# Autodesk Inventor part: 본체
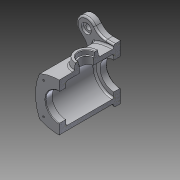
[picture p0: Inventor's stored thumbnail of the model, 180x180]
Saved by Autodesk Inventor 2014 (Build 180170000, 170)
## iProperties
Created: 2016-05
Part Number: 본체
Material: 알루미늄 6061
Document SubType Name: Modeling
Designer: Administrator
Density: 2.71 g/cm^3
Appearance: 알루미늄 - 평지
Mass: 1109.84 g
Surface Area: 864.198 cm^2
Volume: 409.536 cm^3
Author: Administrator
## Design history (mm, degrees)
sketch "스케치1"
  geometry: L1 (0, 0)-(-35.355, 35.355); L2 (0, 0)-(-50.047, 0); L3 (0, 0)-(35.355, 35.355); L4 (0, 0)-(-35.355, -35.355); L5 (0, 0)-(35.355, -35.355); A1 r 86 centre (0, -43.041) between (35.355, 35.355) and (-35.355, 35.355); A2 r 86 centre (-43.041, 0) between (35.355, -35.355) and (35.355, 35.355); A3 r 86 centre (0, 43.041) between (-35.355, -35.355) and (35.355, -35.355); A4 r 86 centre (43.041, 0) between (-35.355, 35.355) and (-35.355, -35.355); 1 further point
  constraints: 10 end point, 8 point on circle, 4 centre point, 3 equal radius, 2 collinear, 1 coincident, 1 horizontal, 1 perpendicular
  dimensions: "d1" = 45 deg angle of L2 L1; "d2" = 45 deg angle of L2 L3; "d3" = 90 deg angle of L4 L1; "d5" = 100 distance of L3.end L4.end; "d6" = 100 distance of L5.end L1.end; "d8" = 86 radius of A1
extrude "돌출1" new body sketch "스케치1" stored distance "d9" = 98; taper "d10" = 0 deg
sketch "스케치2"
  geometry: L1 (69.188, -69.188)-(-69.188, 69.188); L2 (76.705, 76.705)-(-76.705, -76.705); L3 (0, 0)-(0, -85.925); L4 (49, -49)-(-49, -49); L5 (-49, -49)-(-49, 49); L6 (-49, 49)-(49, 49); L7 (49, 49)-(49, -49); C1 r 18 at (49.497, -49.497); C2 r 18 at (-49.497, -49.497); C3 r 18 at (-49.497, 49.497); C4 r 18 at (49.497, 49.497); A1 r 70 centre (0, 0) between (49.497, -49.497) and (-49.497, -49.497); 3 further points
  constraints: 14 end point, 5 centre point, 4 midpoint, 4 point on circle, 4 point on line, 2 coincident, 2 parallel, 2 perpendicular, 1 horizontal, 1 horizontal alignment, 1 vertical, 1 vertical alignment
  dimensions: "d11" = 70 radius of A1; "d12" = 90 deg angle of L2 L1; "d13" = 45 deg angle of L2 L3; "d15" = 18 radius of C2; "d16" = 18 radius of C1; "d17" = 18 radius of C4; "d18" = 18 radius of C3; "d19" = 98 distance of L5.end L6.end
extrude "돌출2" join sketch "스케치2" distance "d20" = 12; taper "d21" = 0 deg
fillet "모깎기1" dims "d22" = 25
node "작업 평면1"
sketch "스케치3"
  geometry: C1 r 20 at (0, 0); 1 further point
  constraints: 1 centre point, 1 coincident
  dimensions: "d24" = 40 diameter of C1
extrude "돌출3" join sketch "스케치3" stored distance "d25" = 12; taper "d26" = 10 deg
sketch "스케치4"
  geometry: 1 further point
hole "구멍1" sketch "스케치4" at (0, 0) diameter "d27" = 50; stored, may be unused: countersink angle "d31" = 90 deg, drill point angle "d33" = 118 deg; dims "d28" = 6, "d29" = 70, "d30" = 37, "d32" = 8
sketch "스케치5"
  geometry: 1 further point
hole "구멍2" sketch "스케치5" at (0, 0) diameter "d34" = 50; stored, may be unused: countersink angle "d38" = 90 deg, drill point angle "d40" = 118 deg; dims "d35" = 6, "d36" = 70, "d37" = 49, "d39" = 8
hole "구멍3" diameter "d43" = 25; stored, may be unused: countersink angle "d47" = 90 deg, drill point angle "d49" = 118 deg; dims "d41" = 10, "d42" = 10, "d44" = 6, "d45" = 30, "d46" = 8, "d48" = 8
sketch "스케치6" dims "d51" = 80
  geometry: L1 (0, 0)-(28.284, 28.284); L2 (0, 0)-(56.29, 0); 1 further point
  constraints: 4 end point, 1 coincident, 1 horizontal, 3 other
  dimensions: "d50" = 45 deg angle of L2 L1
hole "구멍4" sketch "스케치6" at (28.284, 28.284) diameter "d52" = 3.242; stored, may be unused: countersink angle "d56" = 90 deg, drill point angle "d58" = 118 deg; dims "d53" = 7, "d54" = 30, "d55" = 8, "d57" = 10
sketch "스케치7" dims "d62" = 40
  geometry: L1 (0, 0)-(-28.284, -28.284); L2 (0, 0)-(-63.483, 0); 1 further point
  constraints: 4 end point, 1 coincident, 1 horizontal, 3 other
  dimensions: "d63" = 45 deg angle of L2 L1
hole "구멍5" sketch "스케치7" at (-28.284, -28.284) diameter "d64" = 3.242; stored, may be unused: countersink angle "d68" = 90 deg, drill point angle "d70" = 118 deg; dims "d65" = 7, "d66" = 30, "d67" = 8, "d69" = 10
hole "구멍6" diameter "d76" = 10; stored, may be unused: countersink angle "d80" = 90 deg, drill point angle "d82" = 0 deg; dims "d74" = 10, "d75" = 10, "d77" = 7, "d78" = 18, "d79" = 4, "d81" = 10
fillet "모깎기2" dims "d86" = 3
fillet "모깎기3" dims "d87" = 3
fillet "모깎기4" dims "d88" = 3
fillet "모깎기5" dims "d89" = 3
chamfer "모따기1" distance "d90" = 1; stored, may be unused: second distance "d91" = 2, angle "d92" = 45 deg
node "작업 평면2"
sketch "스케치8"
  geometry: 2 further points
  constraints: 1 horizontal alignment, 1 other
  dimensions: "d93" = 29 distance of point (29, 0) point (0, 0)
feature "엠보싱1" sketch "스케치8" dims "d1" = 45 deg, "d2" = 45 deg, "d3" = 90 deg, "d5" = 100, "d6" = 100, "d8" = 86, "d18" = 18, "d94" = 0.5, "d95" = 0
node "솔리드1"
pattern_circular "원형 패턴1" dims angle "d60" = 360 deg
pattern_circular "원형 패턴2" dims angle "d72" = 360 deg
pattern_circular "원형 패턴3" dims angle "d84" = 360 deg
other parameters: "d23" = 55
